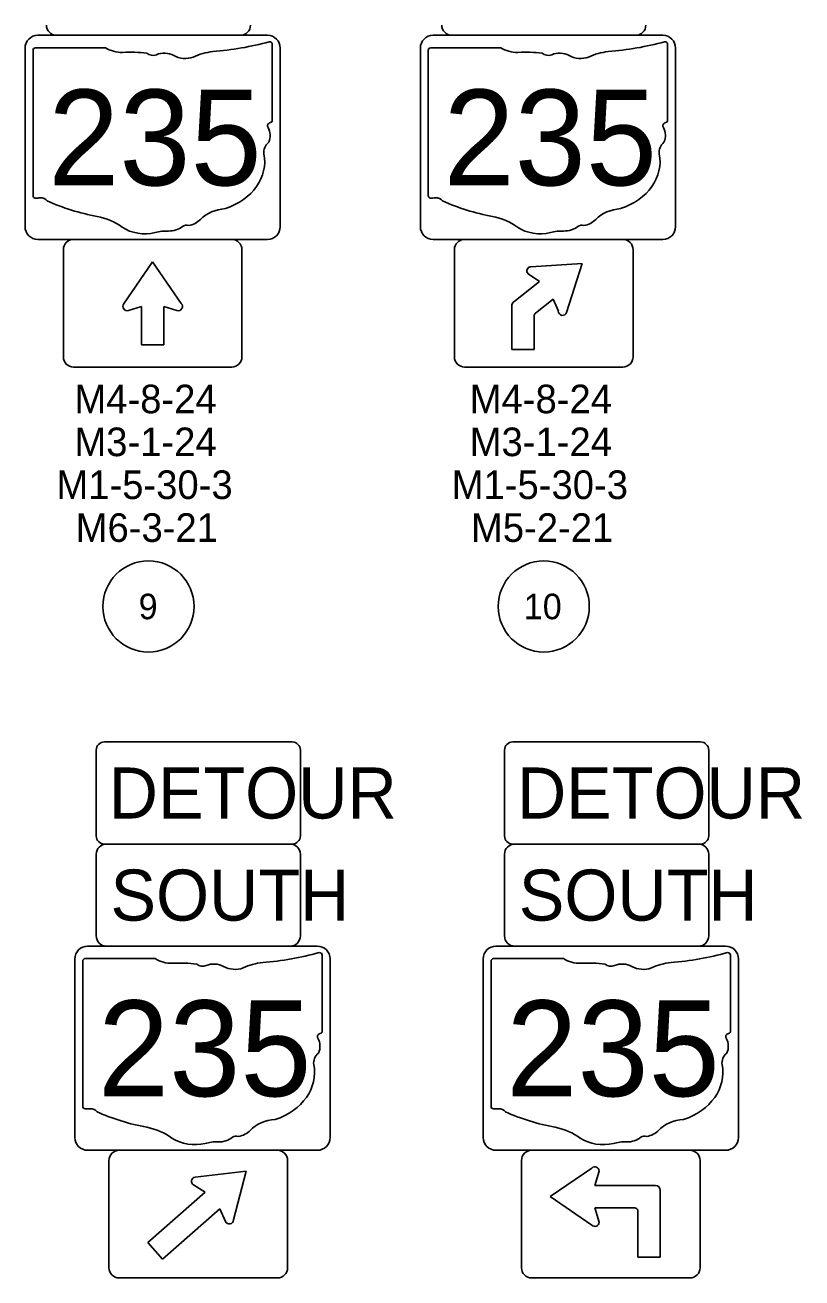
# Model space of a CAD drawing. Extents: x 632.2 to 666.2, y -36.3 to -14.3.
# Drawn here: x 656.93 to 660.73, y -25.43 to -19.3 of the extents above; entities that cross this region are included whole.
import ezdxf

# ---------------------------------------------------------------- set-up
doc = ezdxf.new("R2010")
doc.units = 0
for name, color, linetype in [('Default', 7, 'Continuous'), ('SN_P_Signs', 7, 'Continuous'), ('SN_P_Text', 7, 'Continuous')]:
    doc.layers.add(name, color=color, linetype=linetype)

msp = doc.modelspace()

# ---------------------------------------------------------------- linework, layer by layer
at = {"layer": 'Default'}
for centre in [(657.5297, -22.1449), (659.466, -22.1449)]:
    msp.add_circle(centre, 0.2232, dxfattribs=at)
at = {"layer": 'SN_P_Signs'}
for p, q in [((657.9797, -19.3475), (657.0797, -19.3475)), ((659.916, -19.3475), (659.016, -19.3475)), ((656.9643, -19.421), (656.9643, -20.1326)), ((657.319, -19.4088), (656.9758, -19.4088)), ((658.1362, -19.7634), (658.1362, -19.3912)), ((658.9006, -19.421), (658.9006, -20.1326)), ((659.2553, -19.4088), (658.9121, -19.4088)), ((660.0725, -19.7634), (660.0725, -19.3912)), ((658.136, -19.7633), (658.1362, -19.7634)), ((660.0723, -19.7633), (660.0725, -19.7634)), ((657.1628, -20.3475), (657.9378, -20.3475)), ((659.8535, -20.3475), (659.0785, -20.3475)), ((657.1128, -20.9225), (657.1128, -20.3975)), ((657.9878, -20.3975), (657.9878, -20.9225)), ((659.0285, -20.3975), (659.0285, -20.9225)), ((659.9035, -20.9225), (659.9035, -20.3975)), ((657.4081, -20.6638), (657.5503, -20.4569)), ((657.5503, -20.4569), (657.69, -20.6609)), ((659.4029, -20.4809), (659.403, -20.4809)), ((659.403, -20.4809), (659.6535, -20.4654)), ((659.6535, -20.4654), (659.5781, -20.7049)), ((659.3189, -20.653), (659.4452, -20.5541)), ((659.4452, -20.5541), (659.3895, -20.5165)), ((657.4955, -20.6756), (657.4314, -20.6955)), ((657.4955, -20.8631), (657.4955, -20.6756)), ((657.6691, -20.6955), (657.6049, -20.6756)), ((657.6049, -20.6756), (657.6049, -20.8631)), ((659.3099, -20.8865), (659.3099, -20.6715)), ((659.5126, -20.6404), (659.4254, -20.7088)), ((659.5374, -20.6986), (659.5126, -20.6404)), ((659.4192, -20.7212), (659.4192, -20.8865)), ((657.6049, -20.8631), (657.4955, -20.8631)), ((659.4192, -20.8865), (659.3099, -20.8865)), ((657.9378, -20.9725), (657.1628, -20.9725)), ((659.0785, -20.9725), (659.8535, -20.9725)), ((657.3238, -23.3085), (658.2238, -23.3085)), ((659.3238, -23.3085), (660.2238, -23.3085)), ((657.2738, -23.7585), (657.2738, -23.3585)), ((658.2738, -23.3585), (658.2738, -23.7585)), ((659.2738, -23.7585), (659.2738, -23.3585)), ((660.2738, -23.3585), (660.2738, -23.7585)), ((658.2238, -23.8085), (657.3238, -23.8085)), ((658.3803, -24.2244), (658.3803, -23.8522)), ((660.2238, -23.8085), (659.3238, -23.8085)), ((660.3803, -24.2244), (660.3803, -23.8522)), ((657.2084, -23.8821), (657.2084, -24.5936)), ((657.5631, -23.8698), (657.2199, -23.8698)), ((659.2084, -23.8821), (659.2084, -24.5936)), ((659.5631, -23.8698), (659.2199, -23.8698)), ((658.3801, -24.2243), (658.3803, -24.2244)), ((660.3801, -24.2243), (660.3803, -24.2244)), ((657.3863, -24.8085), (658.1613, -24.8085)), ((659.4069, -24.8085), (660.1819, -24.8085)), ((657.3363, -25.3835), (657.3363, -24.8585)), ((657.7588, -24.9396), (658.0082, -24.9101)), ((658.0082, -24.9101), (657.947, -25.1496)), ((658.2113, -24.8585), (658.2113, -25.3835)), ((659.3569, -25.3835), (659.3569, -24.8585)), ((659.7015, -24.8953), (659.4975, -25.0351)), ((659.7163, -24.9804), (659.7371, -24.9101)), ((660.2319, -24.8585), (660.2319, -25.3835)), ((657.7588, -24.9396), (657.7588, -24.9396)), ((657.5267, -25.2596), (657.8077, -25.0132)), ((657.8077, -25.0132), (657.7504, -24.9781)), ((660.0132, -24.9804), (659.7163, -24.9804)), ((660.0132, -24.9804), (660.0132, -24.9804)), ((660.0366, -25.332), (660.0366, -25.0038)), ((657.8798, -25.0954), (657.5989, -25.3418)), ((657.9071, -25.1568), (657.8798, -25.0955)), ((659.4975, -25.0351), (659.7015, -25.1748)), ((659.7371, -25.1601), (659.7163, -25.0898)), ((659.7163, -25.0898), (659.9116, -25.0898)), ((659.9272, -25.1054), (659.9272, -25.332)), ((657.5989, -25.3418), (657.5267, -25.2596)), ((659.9272, -25.332), (660.0366, -25.332)), ((659.9272, -25.332), (660.0366, -25.332)), ((658.1613, -25.4335), (657.3863, -25.4335)), ((660.1819, -25.4335), (659.4069, -25.4335))]:
    msp.add_line(p, q, dxfattribs=at)
for points in [[(656.9878, -19.3475), (658.1128, -19.3475)], [(658.9241, -19.3475), (660.0491, -19.3475)], [(656.9253, -20.285), (656.9253, -19.41)], [(658.1753, -19.41), (658.1753, -20.285)], [(658.8616, -20.285), (658.8616, -19.41)], [(660.1116, -19.41), (660.1116, -20.285)], [(658.1128, -20.3475), (656.9878, -20.3475)], [(660.0491, -20.3475), (658.9241, -20.3475)], [(658.2338, -22.8085), (657.3138, -22.8085)], [(660.2338, -22.8085), (659.3138, -22.8085)], [(657.2738, -22.8485), (657.2738, -23.2685)], [(658.2738, -23.2685), (658.2738, -22.8485)], [(659.2738, -22.8485), (659.2738, -23.2685)], [(660.2738, -23.2685), (660.2738, -22.8485)], [(657.3138, -23.3085), (658.2338, -23.3085)], [(659.3138, -23.3085), (660.2338, -23.3085)], [(657.2319, -23.8085), (658.3569, -23.8085)], [(659.2319, -23.8085), (660.3569, -23.8085)], [(657.1694, -24.746), (657.1694, -23.871)], [(658.4194, -23.871), (658.4194, -24.746)], [(659.1694, -24.746), (659.1694, -23.871)], [(660.4194, -23.871), (660.4194, -24.746)], [(658.3569, -24.8085), (657.2319, -24.8085)], [(660.3569, -24.8085), (659.2319, -24.8085)]]:
    msp.add_lwpolyline(points, dxfattribs=at)
for centre, radius, start, end in [((657.0797, -19.2975), 0.05, 180, 270), ((657.9797, -19.2975), 0.05, 270, 0), ((659.016, -19.2975), 0.05, 180, 270), ((659.916, -19.2975), 0.05, 270, 0), ((656.9878, -19.41), 0.0625, 90, 180), ((658.1128, -19.41), 0.0625, 0, 90), ((658.9241, -19.41), 0.0625, 90, 180), ((660.0491, -19.41), 0.0625, 0, 90), ((656.9878, -20.285), 0.0625, 180, 270), ((658.1128, -20.285), 0.0625, 270, 0), ((658.9241, -20.285), 0.0625, 180, 270), ((660.0491, -20.285), 0.0625, 270, 0), ((657.1628, -20.3974), 0.05, 90, 180), ((657.9378, -20.3974), 0.05, 0, 90), ((659.0785, -20.3975), 0.05, 90, 180), ((659.8535, -20.3975), 0.05, 0, 90), ((659.4043, -20.5017), 0.0209, 93.59993, 225.00014), ((657.4253, -20.6756), 0.0209, 145.41122, 287.20461), ((657.6753, -20.6756), 0.0209, 252.79539, 45.00956), ((659.3332, -20.6714), 0.0234, 127.78574, 180), ((659.4348, -20.7212), 0.0156, 127.34935, 180), ((659.5582, -20.6986), 0.0209, 180.05091, 342.58035), ((657.1628, -20.9224), 0.05, 180, 270), ((657.9378, -20.9224), 0.05, 270, 0), ((659.0785, -20.9225), 0.05, 180, 270), ((659.8535, -20.9225), 0.05, 270, 360), ((657.3138, -22.8485), 0.04, 90, 180), ((658.2338, -22.8485), 0.04, 0, 90), ((659.3138, -22.8485), 0.04, 90, 180), ((660.2338, -22.8485), 0.04, 0, 90), ((657.3138, -23.2685), 0.04, 180, 270), ((657.3238, -23.3585), 0.05, 90, 180), ((658.2238, -23.3585), 0.05, 0, 90), ((658.2338, -23.2685), 0.04, 270, 0), ((659.3138, -23.2685), 0.04, 180, 270), ((659.3238, -23.3585), 0.05, 90, 180), ((660.2238, -23.3585), 0.05, 0, 90), ((660.2338, -23.2685), 0.04, 270, 0), ((657.3238, -23.7585), 0.05, 180, 270), ((658.2238, -23.7585), 0.05, 270, 0), ((659.3238, -23.7585), 0.05, 180, 270), ((660.2238, -23.7585), 0.05, 270, 0), ((657.2319, -23.871), 0.0625, 90, 180), ((658.3569, -23.871), 0.0625, 0, 90), ((659.2319, -23.871), 0.0625, 90, 180), ((660.3569, -23.871), 0.0625, 0, 90), ((657.2319, -24.746), 0.0625, 180, 270), ((658.3569, -24.746), 0.0625, 270, 0), ((659.2319, -24.746), 0.0625, 180, 270), ((660.3569, -24.746), 0.0625, 270, 0), ((657.3863, -24.8585), 0.05, 90, 180), ((658.1613, -24.8585), 0.05, 0, 90), ((659.4069, -24.8585), 0.05, 90, 180), ((660.1819, -24.8585), 0.05, 0, 90), ((659.7163, -24.91), 0.0209, 0.00165, 134.99986), ((657.7613, -24.9603), 0.0209, 96.66992, 238.46331), ((660.0132, -25.0038), 0.0234, 0, 90), ((659.9116, -25.1054), 0.0156, 0, 90), ((657.9261, -25.1483), 0.0209, 204.05409, 356.26826), ((659.7163, -25.16), 0.0209, 225.00014, 0.00165), ((657.3863, -25.3835), 0.05, 180, 270), ((658.1613, -25.3835), 0.05, 270, 0), ((659.4069, -25.3835), 0.05, 180, 270), ((660.1819, -25.3835), 0.05, 270, 360)]:
    msp.add_arc(centre, radius, start, end, dxfattribs=at)
for centre, major_axis, start_param, end_param in [((657.7187, -18.4387), (1.2427, 0), 4.814394, 5.042369), ((658.1232, -19.3896), (0.013, 0), 6.141152, 7.989035), ((659.655, -18.4387), (1.2427, 0), 4.814394, 5.042369), ((660.0595, -19.3896), (0.013, 0), 6.141152, 7.989035), ((656.9777, -19.4195), (0.0136, 0), 1.712693, 3.28349), ((657.4008, -19.3262), (0.1317, 0), 4.042523, 4.731795), ((657.4444, -19.8083), (0.4727, 0), 1.404758, 1.657858), ((657.5517, -19.4158), (0.038, 0), 3.836095, 5.185415), ((657.6075, -19.4981), (0.079, 0), 0.950623, 2.079405), ((657.7094, -19.3853), (0.095, 0), 4.081561, 5.145723), ((657.8772, -19.6261), (0.25, 0), 1.699011, 2.107814), ((658.914, -19.4195), (0.0136, 0), 1.712693, 3.28349), ((659.337, -19.3262), (0.1317, 0), 4.042523, 4.731795), ((659.3807, -19.8083), (0.4727, 0), 1.404758, 1.657858), ((659.488, -19.4158), (0.038, 0), 3.836095, 5.185415), ((659.5438, -19.4981), (0.079, 0), 0.950623, 2.079405), ((659.6457, -19.3853), (0.095, 0), 4.081561, 5.145723), ((659.8135, -19.6261), (0.25, 0), 1.699011, 2.107814), ((658.1331, -19.7907), (0.0202, 0), 1.883978, 3.671073), ((658.0047, -19.8378), (0.1212, 0), 5.934695, 6.695948), ((658.1222, -19.7648), (0.014, 0), 5.05454, 6.418171), ((660.0694, -19.7907), (0.0202, 0), 1.883978, 3.671073), ((659.941, -19.8378), (0.1212, 0), 5.934695, 6.695948), ((660.0585, -19.7648), (0.014, 0), 5.05454, 6.418171), ((658.1829, -19.9192), (0.0882, 0), 2.387724, 3.262537), ((660.1192, -19.9192), (0.0882, 0), 2.387724, 3.262537), ((657.7883, -19.9665), (0.3108, 0), 5.101752, 6.440018), ((659.7246, -19.9665), (0.3108, 0), 5.101752, 6.440018), ((656.9778, -20.1341), (0.0137, 0), 3.00124, 4.508301), ((656.9799, -20.0613), (0.1045, 0), 4.665946, 4.897461), ((657.0013, -20.1736), (0.0377, 0), 0.519207, 1.627899), ((657.4771, -19.5343), (0.8974, 0), 4.195997, 4.488961), ((658.9141, -20.1341), (0.0137, 0), 3.00124, 4.508301), ((658.9162, -20.0613), (0.1045, 0), 4.665946, 4.897461), ((658.9376, -20.1736), (0.0377, 0), 0.519207, 1.627899), ((659.4134, -19.5343), (0.8974, 0), 4.195997, 4.488961), ((657.2096, -20.4522), (0.2808, 0), 0.823519, 1.323587), ((657.9194, -20.3323), (0.1702, 0), 1.647645, 2.488434), ((659.1459, -20.4522), (0.2808, 0), 0.823519, 1.323587), ((659.8557, -20.3323), (0.1702, 0), 1.647645, 2.488434), ((657.5133, -20.1772), (0.1782, 0), 4.026481, 4.996735), ((657.6162, -20.4232), (0.1464, 0), 1.495662, 1.94098), ((657.6292, -20.2304), (0.0949, 0), 4.691044, 5.507374), ((657.7151, -20.2994), (0.0267, 0), 1.147584, 2.315152), ((657.7037, -20.2015), (0.1004, 0), 4.937069, 5.64225), ((659.4496, -20.1772), (0.1782, 0), 4.026481, 4.996735), ((659.5525, -20.4232), (0.1464, 0), 1.495662, 1.94098), ((659.5655, -20.2304), (0.0949, 0), 4.691044, 5.507374), ((659.6514, -20.2994), (0.0267, 0), 1.147584, 2.315152), ((659.64, -20.2015), (0.1004, 0), 4.937069, 5.64225), ((657.9628, -22.8997), (1.2427, 0), 4.814394, 5.042369), ((658.3673, -23.8506), (0.013, 0), 6.141152, 7.989035), ((659.9628, -22.8997), (1.2427, 0), 4.814394, 5.042369), ((660.3673, -23.8506), (0.013, 0), 6.141152, 7.989035), ((657.2218, -23.8805), (0.0136, 0), 1.712693, 3.28349), ((657.6449, -23.7872), (0.1317, 0), 4.042523, 4.731795), ((657.6885, -24.2693), (0.4727, 0), 1.404758, 1.657858), ((657.7958, -23.8769), (0.038, 0), 3.836095, 5.185415), ((657.8516, -23.9591), (0.079, 0), 0.950623, 2.079405), ((657.9535, -23.8463), (0.095, 0), 4.081561, 5.145723), ((658.1213, -24.0871), (0.25, 0), 1.699011, 2.107814), ((659.2218, -23.8805), (0.0136, 0), 1.712693, 3.28349), ((659.6449, -23.7872), (0.1317, 0), 4.042523, 4.731795), ((659.6885, -24.2693), (0.4727, 0), 1.404758, 1.657858), ((659.7958, -23.8769), (0.038, 0), 3.836095, 5.185415), ((659.8516, -23.9591), (0.079, 0), 0.950623, 2.079405), ((659.9535, -23.8463), (0.095, 0), 4.081561, 5.145723), ((660.1213, -24.0871), (0.25, 0), 1.699011, 2.107814), ((658.3772, -24.2517), (0.0202, 0), 1.883978, 3.671073), ((658.3663, -24.2258), (0.014, 0), 5.05454, 6.418171), ((660.3772, -24.2517), (0.0202, 0), 1.883978, 3.671073), ((660.3663, -24.2258), (0.014, 0), 5.05454, 6.418171), ((658.2488, -24.2988), (0.1212, 0), 5.934695, 6.695948), ((660.2488, -24.2988), (0.1212, 0), 5.934695, 6.695948), ((658.427, -24.3802), (0.0882, 0), 2.387724, 3.262537), ((660.427, -24.3802), (0.0882, 0), 2.387724, 3.262537), ((658.0324, -24.4275), (0.3108, 0), 5.101752, 6.440018), ((660.0324, -24.4275), (0.3108, 0), 5.101752, 6.440018), ((657.222, -24.5952), (0.0137, 0), 3.00124, 4.508301), ((657.224, -24.5224), (0.1045, 0), 4.665946, 4.897461), ((657.2454, -24.6346), (0.0377, 0), 0.519207, 1.627899), ((659.222, -24.5952), (0.0137, 0), 3.00124, 4.508301), ((659.224, -24.5224), (0.1045, 0), 4.665946, 4.897461), ((659.2454, -24.6346), (0.0377, 0), 0.519207, 1.627899), ((657.7212, -23.9954), (0.8974, 0), 4.195997, 4.488961), ((658.1635, -24.7934), (0.1702, 0), 1.647645, 2.488434), ((659.7212, -23.9954), (0.8974, 0), 4.195997, 4.488961), ((660.1635, -24.7934), (0.1702, 0), 1.647645, 2.488434), ((657.4537, -24.9133), (0.2808, 0), 0.823519, 1.323587), ((657.9478, -24.6626), (0.1004, 0), 4.937069, 5.64225), ((659.4537, -24.9133), (0.2808, 0), 0.823519, 1.323587), ((659.9478, -24.6626), (0.1004, 0), 4.937069, 5.64225), ((657.7574, -24.6382), (0.1782, 0), 4.026481, 4.996735), ((657.8603, -24.8842), (0.1464, 0), 1.495662, 1.94098), ((657.8733, -24.6915), (0.0949, 0), 4.691044, 5.507374), ((657.9592, -24.7604), (0.0267, 0), 1.147584, 2.315152), ((659.7574, -24.6382), (0.1782, 0), 4.026481, 4.996735), ((659.8603, -24.8842), (0.1464, 0), 1.495662, 1.94098), ((659.8733, -24.6915), (0.0949, 0), 4.691044, 5.507374), ((659.9592, -24.7604), (0.0267, 0), 1.147584, 2.315152)]:
    msp.add_ellipse(centre, major_axis=major_axis, ratio=0.8, start_param=start_param, end_param=end_param, dxfattribs=at)

# ---------------------------------------------------------------- texts
at = {"layer": 'Default'}
for s, p in [('9', (657.4816, -22.2074)), ('10', (659.3681, -22.2074))]:
    msp.add_text(s, height=0.125, dxfattribs=at).set_placement(p)
at = {"layer": 'SN_P_Signs'}
for s, height, p in [('235', 0.46875, (657.0385, -20.0824)), ('235', 0.46875, (658.9748, -20.0824)), ('DETOUR', 0.25, (657.3346, -23.1835)), ('DETOUR', 0.25, (659.3346, -23.1835)), ('SOUTH', 0.25, (657.3438, -23.6835)), ('SOUTH', 0.25, (659.3438, -23.6835)), ('235', 0.46875, (657.2826, -24.5434)), ('235', 0.46875, (659.2826, -24.5434))]:
    msp.add_text(s, height=height, dxfattribs=at).set_placement(p)
at = {"layer": 'SN_P_Text'}
for s, p in [('M4-8-24', (657.1669, -21.1987)), ('M4-8-24', (659.1032, -21.1987)), ('M3-1-24', (657.1669, -21.4087)), ('M3-1-24', (659.1032, -21.4087)), ('M1-5-30-3', (657.0787, -21.6187)), ('M1-5-30-3', (659.015, -21.6187)), ('M6-3-21', (657.1732, -21.8287)), ('M5-2-21', (659.1095, -21.8287))]:
    msp.add_text(s, height=0.14, dxfattribs=at).set_placement(p)

doc.saveas('drawing.dxf')
